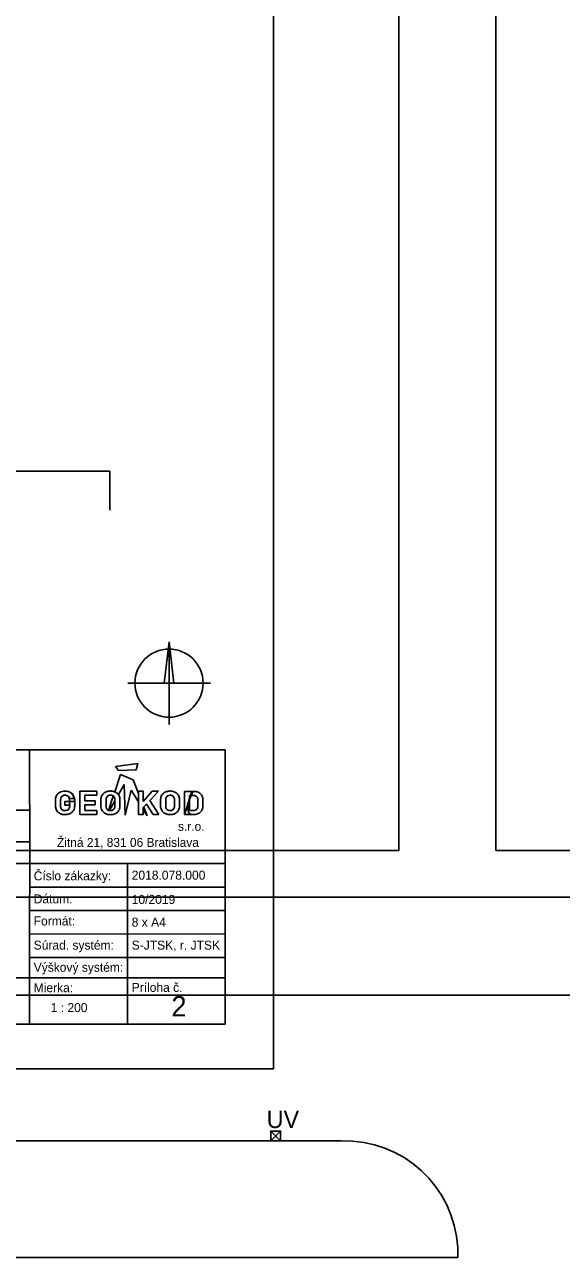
# Model space of a CAD drawing. Extents: x -264222 to -263676, y -1242344 to -1242060.
# Drawn here: x -264066.8 to -264039.2, y -1242315 to -1242251.5 of the extents above; entities that cross this region are included whole.
import ezdxf

# ---------------------------------------------------------------- set-up
doc = ezdxf.new("R2010")
doc.units = 0
for name, color, linetype in [('KOORDINACNA_SITUACIA_DSP', 7, 'Continuous'), ('PROJEKT_DRS_OBRUBNIKY_KOMUNIKACIE', 7, 'Continuous'), ('PROJEKT_DRS_UV_STAVBY', 7, 'Continuous'), ('RAM_NA_TLAC_8xA4_1-200', 7, 'Continuous'), ('ROZPISKA', 7, 'Continuous')]:
    doc.layers.add(name, color=color, linetype=linetype)

msp = doc.modelspace()

# ---------------------------------------------------------------- linework, layer by layer
at = {"layer": 'KOORDINACNA_SITUACIA_DSP'}
for p, q in [((-264062.458, -1242274.482), (-264102.778, -1242274.482)), ((-264062.458, -1242276.492), (-264062.458, -1242274.482))]:
    msp.add_line(p, q, dxfattribs=at)
at = {"layer": 'PROJEKT_DRS_OBRUBNIKY_KOMUNIKACIE'}
for p, q in [((-263971.068, -1242301.482), (-264112.961, -1242301.482)), ((-264050.531, -1242308.982), (-264119.571, -1242308.982)), ((-264115.886, -1242314.982), (-264044.531, -1242314.982)), ((-264044.531, -1242314.982), (-264044.531, -1242314.482))]:
    msp.add_line(p, q, dxfattribs=at)
for points in [[(-264117.668, -1242187.932), (-264047.568, -1242187.932), (-264047.568, -1242294.032), (-264117.668, -1242294.032), (-264117.668, -1242187.932)], [(-264042.568, -1242294.032), (-263972.468, -1242294.032), (-263972.468, -1242187.932), (-264042.568, -1242187.932), (-264042.568, -1242294.032)], [(-263965.143, -1242296.432), (-264120.018, -1242296.432), (-264120.282, -1242296.432)]]:
    msp.add_lwpolyline(points, dxfattribs=at)
msp.add_arc((-264050.347, -1242314.804), 5.825, 3.17009, 91.80902, dxfattribs=at)
at = {"layer": 'PROJEKT_DRS_UV_STAVBY'}
msp.add_lwpolyline([(-264054.163, -1242308.982), (-264054.163, -1242308.482), (-264053.663, -1242308.482), (-264053.663, -1242308.982), (-264054.163, -1242308.982), (-264053.663, -1242308.482), (-264054.163, -1242308.482), (-264053.663, -1242308.982)], dxfattribs=at)
at = {"layer": 'RAM_NA_TLAC_8xA4_1-200'}
msp.add_lwpolyline([(-264222.03, -1242186.466), (-264054.03, -1242186.466), (-264054.03, -1242305.266), (-264222.03, -1242305.266)], close=True, dxfattribs=at)
at = {"layer": 'ROZPISKA'}
for p, q in [((-264059.408, -1242283.272), (-264059.66, -1242285.404)), ((-264059.408, -1242283.272), (-264059.408, -1242287.536)), ((-264059.408, -1242283.272), (-264059.155, -1242285.403)), ((-264061.539, -1242285.404), (-264057.276, -1242285.403)), ((-264093.815, -1242288.848), (-264056.508, -1242288.848)), ((-264066.59, -1242294.494), (-264066.592, -1242288.847)), ((-264056.508, -1242288.848), (-264056.508, -1242302.965)), ((-264062.207, -1242291.004), (-264061.914, -1242290.118)), ((-264061.914, -1242290.118), (-264061.264, -1242290.394)), ((-264062.444, -1242290.962), (-264062.423, -1242290.961)), ((-264061.728, -1242290.622), (-264062.019, -1242291.144)), ((-264061.671, -1242292.202), (-264061.728, -1242290.622)), ((-264061.359, -1242290.921), (-264061.671, -1242292.202)), ((-264060.989, -1242291.517), (-264061.359, -1242290.921)), ((-264061.264, -1242290.394), (-264060.989, -1242291.093)), ((-264060.735, -1242290.977), (-264060.989, -1242290.977)), ((-264060.274, -1242290.977), (-264060.735, -1242291.499)), ((-264060.735, -1242291.499), (-264060.735, -1242290.977)), ((-264060.396, -1242291.457), (-264059.957, -1242290.977)), ((-264059.957, -1242290.977), (-264060.274, -1242290.977)), ((-264064.272, -1242291.347), (-264064.537, -1242291.347)), ((-264064.537, -1242291.347), (-264064.272, -1242291.347)), ((-264062.279, -1242291.223), (-264062.522, -1242291.959)), ((-264062.44, -1242291.175), (-264062.426, -1242291.175)), ((-264062.44, -1242291.175), (-264062.426, -1242291.175)), ((-264060.989, -1242291.093), (-264060.989, -1242291.517)), ((-264059.933, -1242292.172), (-264060.396, -1242291.457)), ((-264058.615, -1242290.98), (-264058.234, -1242290.98)), ((-264058.615, -1242292.172), (-264058.615, -1242290.98)), ((-264058.615, -1242290.98), (-264058.615, -1242292.172)), ((-264058.234, -1242290.98), (-264058.615, -1242290.98)), ((-264058.354, -1242291.187), (-264058.354, -1242291.965)), ((-264058.354, -1242291.187), (-264058.354, -1242291.965)), ((-264093.817, -1242291.946), (-264066.591, -1242291.946)), ((-264060.535, -1242292.248), (-264060.735, -1242291.927)), ((-264060.714, -1242291.793), (-264060.535, -1242292.248)), ((-264060.234, -1242292.172), (-264059.933, -1242292.172)), ((-264093.816, -1242293.587), (-264066.592, -1242293.587)), ((-264093.818, -1242294.699), (-264066.588, -1242294.696)), ((-264066.59, -1242294.494), (-264066.591, -1242298.126)), ((-264066.588, -1242294.696), (-264056.507, -1242294.696)), ((-264061.55, -1242294.697), (-264061.549, -1242298.328)), ((-264066.59, -1242295.907), (-264056.508, -1242295.908)), ((-264066.593, -1242297.116), (-264056.507, -1242297.116)), ((-264066.593, -1242298.327), (-264056.506, -1242298.328)), ((-264066.591, -1242298.126), (-264066.591, -1242302.964)), ((-264061.549, -1242298.328), (-264061.548, -1242302.964)), ((-264066.591, -1242299.537), (-264056.507, -1242299.536)), ((-264093.816, -1242300.585), (-264056.507, -1242300.584)), ((-264093.816, -1242302.965), (-264056.508, -1242302.965))]:
    msp.add_line(p, q, dxfattribs=at)
for points in [[(-264059.408, -1242283.272), (-264059.155, -1242285.403), (-264059.408, -1242285.403)], [(-264062.173, -1242289.707), (-264061.017, -1242289.541), (-264061.098, -1242289.871), (-264062.019, -1242289.9)], [(-264064.01, -1242290.971), (-264064.01, -1242292.172), (-264063.131, -1242292.172), (-264063.131, -1242291.96), (-264063.746, -1242291.96), (-264063.746, -1242291.673), (-264063.22, -1242291.673), (-264063.22, -1242291.464), (-264063.746, -1242291.464), (-264063.746, -1242291.184), (-264063.131, -1242291.184), (-264063.131, -1242290.971)]]:
    msp.add_lwpolyline(points, close=True, dxfattribs=at)
for points in [[(-264060.989, -1242290.977), (-264060.989, -1242292.172), (-264060.735, -1242292.172), (-264060.735, -1242291.815), (-264060.565, -1242291.635), (-264060.234, -1242292.172)], [(-264064.528, -1242291.7), (-264064.778, -1242291.7), (-264064.778, -1242291.502), (-264064.269, -1242291.502)], [(-264064.269, -1242291.502), (-264064.778, -1242291.502), (-264064.778, -1242291.7), (-264064.528, -1242291.7)], [(-264062.481, -1242291.97), (-264062.2, -1242291.467)], [(-264062.2, -1242291.467), (-264062.2, -1242291.441), (-264062.201, -1242291.408), (-264062.204, -1242291.378), (-264062.209, -1242291.349), (-264062.216, -1242291.322), (-264062.226, -1242291.293), (-264062.242, -1242291.264), (-264062.259, -1242291.242), (-264062.279, -1242291.223)], [(-264062.019, -1242291.144), (-264062.028, -1242291.133), (-264062.043, -1242291.116), (-264062.058, -1242291.101), (-264062.076, -1242291.085), (-264062.093, -1242291.071), (-264062.113, -1242291.057), (-264062.129, -1242291.046), (-264062.147, -1242291.035), (-264062.168, -1242291.023), (-264062.187, -1242291.012), (-264062.207, -1242291.004)], [(-264062.522, -1242291.959), (-264062.515, -1242291.961), (-264062.507, -1242291.964), (-264062.5, -1242291.966), (-264062.493, -1242291.968), (-264062.486, -1242291.969), (-264062.481, -1242291.97)], [(-264060.735, -1242291.927), (-264060.735, -1242291.815), (-264060.714, -1242291.793)]]:
    msp.add_lwpolyline(points, dxfattribs=at)
msp.add_circle((-264059.408, -1242285.404), 1.756, dxfattribs=at)
for points in [[(-264064.269, -1242291.502), (-264064.268, -1242291.654), (-264064.272, -1242291.79), (-264064.299, -1242291.91), (-264064.358, -1242292.007), (-264064.447, -1242292.089), (-264064.54, -1242292.143), (-264064.665, -1242292.175), (-264064.777, -1242292.182), (-264064.894, -1242292.175), (-264065.01, -1242292.136), (-264065.112, -1242292.07), (-264065.189, -1242291.992), (-264065.24, -1242291.887), (-264065.263, -1242291.77), (-264065.267, -1242291.693), (-264065.267, -1242291.456), (-264065.259, -1242291.327), (-264065.224, -1242291.219), (-264065.166, -1242291.125), (-264065.049, -1242291.032), (-264064.925, -1242290.978), (-264064.781, -1242290.962), (-264064.63, -1242290.974), (-264064.47, -1242291.04), (-264064.346, -1242291.156), (-264064.272, -1242291.347), (-264064.269, -1242291.502), (-264064.272, -1242291.347)], [(-264064.272, -1242291.347), (-264064.346, -1242291.156), (-264064.47, -1242291.04), (-264064.63, -1242290.974), (-264064.781, -1242290.962), (-264064.925, -1242290.978), (-264065.049, -1242291.032), (-264065.166, -1242291.125), (-264065.224, -1242291.219), (-264065.259, -1242291.327), (-264065.267, -1242291.456), (-264065.267, -1242291.693), (-264065.263, -1242291.77), (-264065.24, -1242291.887), (-264065.189, -1242291.992), (-264065.112, -1242292.07), (-264065.01, -1242292.136), (-264064.894, -1242292.175), (-264064.777, -1242292.182), (-264064.665, -1242292.175), (-264064.54, -1242292.143), (-264064.447, -1242292.089), (-264064.358, -1242292.007), (-264064.299, -1242291.91), (-264064.272, -1242291.79), (-264064.268, -1242291.654), (-264064.269, -1242291.502), (-264064.272, -1242291.347), (-264064.269, -1242291.502)], [(-264062.423, -1242290.961), (-264062.417, -1242290.961), (-264062.381, -1242290.96), (-264062.314, -1242290.976), (-264062.224, -1242290.992), (-264062.139, -1242291.039), (-264062.062, -1242291.092), (-264061.998, -1242291.167), (-264061.962, -1242291.25), (-264061.938, -1242291.342), (-264061.939, -1242291.487), (-264061.935, -1242291.636), (-264061.938, -1242291.782), (-264061.951, -1242291.875), (-264061.986, -1242291.952), (-264062.03, -1242292.02), (-264062.09, -1242292.072), (-264062.155, -1242292.12), (-264062.236, -1242292.152), (-264062.324, -1242292.178), (-264062.419, -1242292.184), (-264062.508, -1242292.178), (-264062.588, -1242292.171), (-264062.656, -1242292.14), (-264062.721, -1242292.102), (-264062.783, -1242292.062), (-264062.838, -1242292.004), (-264062.883, -1242291.926), (-264062.915, -1242291.831), (-264062.928, -1242291.675), (-264062.914, -1242291.529), (-264062.922, -1242291.389), (-264062.91, -1242291.31), (-264062.892, -1242291.232), (-264062.853, -1242291.162), (-264062.803, -1242291.105), (-264062.749, -1242291.055), (-264062.681, -1242291.018), (-264062.603, -1242290.983), (-264062.521, -1242290.966), (-264062.467, -1242290.963), (-264062.444, -1242290.962)], [(-264059.348, -1242290.961), (-264059.436, -1242290.967), (-264059.53, -1242290.988), (-264059.608, -1242291.02), (-264059.671, -1242291.057), (-264059.726, -1242291.106), (-264059.774, -1242291.162), (-264059.813, -1242291.233), (-264059.833, -1242291.311), (-264059.843, -1242291.387), (-264059.843, -1242291.471), (-264059.846, -1242291.729), (-264059.836, -1242291.825), (-264059.801, -1242291.932), (-264059.756, -1242292.008), (-264059.709, -1242292.057), (-264059.641, -1242292.104), (-264059.58, -1242292.139), (-264059.514, -1242292.166), (-264059.434, -1242292.178), (-264059.348, -1242292.182), (-264059.246, -1242292.174), (-264059.155, -1242292.149), (-264059.084, -1242292.118), (-264059.012, -1242292.069), (-264058.957, -1242292.018), (-264058.914, -1242291.954), (-264058.879, -1242291.872), (-264058.865, -1242291.788), (-264058.861, -1242291.684), (-264058.863, -1242291.436), (-264058.867, -1242291.34), (-264058.887, -1242291.254), (-264058.928, -1242291.166), (-264058.983, -1242291.1), (-264059.069, -1242291.037), (-264059.147, -1242290.998), (-264059.239, -1242290.975), (-264059.33, -1242290.961), (-264059.348, -1242290.961), (-264059.348, -1242290.961), (-264059.348, -1242290.961)], [(-264064.535, -1242291.347), (-264064.56, -1242291.281), (-264064.619, -1242291.217), (-264064.698, -1242291.18), (-264064.778, -1242291.174), (-264064.858, -1242291.184), (-264064.922, -1242291.221), (-264064.968, -1242291.272), (-264064.992, -1242291.326), (-264064.994, -1242291.408), (-264065, -1242291.497), (-264065.001, -1242291.604), (-264065, -1242291.73), (-264064.99, -1242291.823), (-264064.955, -1242291.897), (-264064.904, -1242291.94), (-264064.844, -1242291.965), (-264064.78, -1242291.973), (-264064.704, -1242291.969), (-264064.625, -1242291.936), (-264064.568, -1242291.882), (-264064.535, -1242291.819), (-264064.527, -1242291.748), (-264064.528, -1242291.7), (-264064.535, -1242291.347), (-264064.528, -1242291.7)], [(-264064.528, -1242291.7), (-264064.527, -1242291.748), (-264064.535, -1242291.819), (-264064.568, -1242291.882), (-264064.625, -1242291.936), (-264064.704, -1242291.969), (-264064.78, -1242291.973), (-264064.844, -1242291.965), (-264064.904, -1242291.94), (-264064.955, -1242291.897), (-264064.99, -1242291.823), (-264065, -1242291.73), (-264065.001, -1242291.604), (-264065, -1242291.497), (-264064.994, -1242291.408), (-264064.992, -1242291.326), (-264064.968, -1242291.272), (-264064.922, -1242291.221), (-264064.858, -1242291.184), (-264064.778, -1242291.174), (-264064.698, -1242291.18), (-264064.619, -1242291.217), (-264064.56, -1242291.281), (-264064.535, -1242291.347), (-264064.528, -1242291.7), (-264064.535, -1242291.347)], [(-264062.426, -1242291.175), (-264062.415, -1242291.175), (-264062.387, -1242291.175), (-264062.34, -1242291.186), (-264062.287, -1242291.213), (-264062.24, -1242291.259), (-264062.21, -1242291.326), (-264062.198, -1242291.399), (-264062.2, -1242291.481), (-264062.198, -1242291.566), (-264062.201, -1242291.653), (-264062.197, -1242291.734), (-264062.208, -1242291.803), (-264062.224, -1242291.864), (-264062.263, -1242291.919), (-264062.32, -1242291.957), (-264062.381, -1242291.973), (-264062.431, -1242291.97), (-264062.476, -1242291.973), (-264062.524, -1242291.961), (-264062.572, -1242291.932), (-264062.617, -1242291.888), (-264062.648, -1242291.823), (-264062.659, -1242291.745), (-264062.655, -1242291.651), (-264062.657, -1242291.545), (-264062.655, -1242291.444), (-264062.652, -1242291.362), (-264062.639, -1242291.297), (-264062.603, -1242291.244), (-264062.554, -1242291.203), (-264062.497, -1242291.178), (-264062.457, -1242291.175), (-264062.44, -1242291.175)], [(-264062.426, -1242291.175), (-264062.415, -1242291.175), (-264062.387, -1242291.175), (-264062.34, -1242291.186), (-264062.287, -1242291.213), (-264062.24, -1242291.259), (-264062.21, -1242291.326), (-264062.198, -1242291.399), (-264062.2, -1242291.481), (-264062.198, -1242291.566), (-264062.201, -1242291.653), (-264062.197, -1242291.734), (-264062.208, -1242291.803), (-264062.224, -1242291.864), (-264062.263, -1242291.919), (-264062.32, -1242291.957), (-264062.381, -1242291.973), (-264062.431, -1242291.97), (-264062.476, -1242291.973), (-264062.524, -1242291.961), (-264062.572, -1242291.932), (-264062.617, -1242291.888), (-264062.648, -1242291.823), (-264062.659, -1242291.745), (-264062.655, -1242291.651), (-264062.657, -1242291.545), (-264062.655, -1242291.444), (-264062.652, -1242291.362), (-264062.639, -1242291.297), (-264062.603, -1242291.244), (-264062.554, -1242291.203), (-264062.497, -1242291.178), (-264062.457, -1242291.175), (-264062.44, -1242291.175)], [(-264059.35, -1242291.175), (-264059.414, -1242291.18), (-264059.478, -1242291.207), (-264059.527, -1242291.248), (-264059.558, -1242291.295), (-264059.574, -1242291.36), (-264059.578, -1242291.432), (-264059.58, -1242291.541), (-264059.58, -1242291.664), (-264059.58, -1242291.748), (-264059.568, -1242291.823), (-264059.535, -1242291.889), (-264059.492, -1242291.932), (-264059.447, -1242291.959), (-264059.396, -1242291.971), (-264059.355, -1242291.971), (-264059.314, -1242291.971), (-264059.249, -1242291.954), (-264059.185, -1242291.911), (-264059.152, -1242291.864), (-264059.134, -1242291.805), (-264059.124, -1242291.737), (-264059.124, -1242291.66), (-264059.123, -1242291.563), (-264059.124, -1242291.475), (-264059.124, -1242291.405), (-264059.14, -1242291.319), (-264059.167, -1242291.262), (-264059.214, -1242291.215), (-264059.269, -1242291.186), (-264059.316, -1242291.176), (-264059.35, -1242291.175), (-264059.35, -1242291.175), (-264059.35, -1242291.175)], [(-264058.234, -1242290.98), (-264058.109, -1242290.98), (-264058.032, -1242290.985), (-264057.975, -1242290.996), (-264057.901, -1242291.021), (-264057.83, -1242291.061), (-264057.759, -1242291.127), (-264057.707, -1242291.203), (-264057.681, -1242291.273), (-264057.665, -1242291.383), (-264057.664, -1242291.437), (-264057.663, -1242291.675), (-264057.666, -1242291.753), (-264057.672, -1242291.816), (-264057.683, -1242291.884), (-264057.717, -1242291.967), (-264057.776, -1242292.044), (-264057.864, -1242292.113), (-264057.936, -1242292.145), (-264058.009, -1242292.165), (-264058.07, -1242292.172), (-264058.092, -1242292.172), (-264058.615, -1242292.172), (-264058.234, -1242290.98), (-264058.615, -1242292.172)], [(-264058.615, -1242292.172), (-264058.092, -1242292.172), (-264058.07, -1242292.172), (-264058.009, -1242292.165), (-264057.936, -1242292.145), (-264057.864, -1242292.113), (-264057.776, -1242292.044), (-264057.717, -1242291.967), (-264057.683, -1242291.884), (-264057.672, -1242291.816), (-264057.666, -1242291.753), (-264057.663, -1242291.675), (-264057.664, -1242291.437), (-264057.665, -1242291.383), (-264057.681, -1242291.273), (-264057.707, -1242291.203), (-264057.759, -1242291.127), (-264057.83, -1242291.061), (-264057.901, -1242291.021), (-264057.975, -1242290.996), (-264058.032, -1242290.985), (-264058.109, -1242290.98), (-264058.234, -1242290.98), (-264058.615, -1242292.172), (-264058.234, -1242290.98)], [(-264058.354, -1242291.965), (-264058.278, -1242291.965), (-264058.198, -1242291.966), (-264058.115, -1242291.965), (-264058.1, -1242291.966), (-264058.07, -1242291.959), (-264058.022, -1242291.935), (-264057.961, -1242291.892), (-264057.932, -1242291.818), (-264057.923, -1242291.738), (-264057.924, -1242291.626), (-264057.923, -1242291.498), (-264057.924, -1242291.394), (-264057.93, -1242291.324), (-264057.958, -1242291.275), (-264058.011, -1242291.225), (-264058.07, -1242291.199), (-264058.152, -1242291.187), (-264058.207, -1242291.187), (-264058.319, -1242291.188), (-264058.354, -1242291.187)], [(-264058.354, -1242291.965), (-264058.278, -1242291.965), (-264058.198, -1242291.966), (-264058.115, -1242291.965), (-264058.1, -1242291.966), (-264058.07, -1242291.959), (-264058.022, -1242291.935), (-264057.961, -1242291.892), (-264057.932, -1242291.818), (-264057.923, -1242291.738), (-264057.924, -1242291.626), (-264057.923, -1242291.498), (-264057.924, -1242291.394), (-264057.93, -1242291.324), (-264057.958, -1242291.275), (-264058.011, -1242291.225), (-264058.07, -1242291.199), (-264058.152, -1242291.187), (-264058.207, -1242291.187), (-264058.319, -1242291.188), (-264058.354, -1242291.187)]]:
    msp.add_open_spline(points, degree=3, dxfattribs=at)

# ---------------------------------------------------------------- texts
at = {"layer": 'PROJEKT_DRS_UV_STAVBY'}
msp.add_text('UV', height=0.9, rotation=359.8587, dxfattribs=at).set_placement((-264054.378, -1242308.32))
at = {"layer": 'ROZPISKA'}
for s, height, p in [('s.r.o.', 0.4598, (-264058.946, -1242293.012)), ('Žitná 21, 831 06 Bratislava', 0.4598, (-264065.182, -1242293.84)), ('Číslo zákazky:', 0.46361, (-264066.383, -1242295.562)), ('Dátum:', 0.4637, (-264066.383, -1242296.749)), ('Formát:', 0.4637, (-264066.383, -1242297.888)), ('Súrad. systém:', 0.46361, (-264066.383, -1242299.133)), ('Výškový systém:', 0.46361, (-264066.383, -1242300.272)), ('Mierka:', 0.4637, (-264066.383, -1242301.325)), ('Príloha č.', 0.4636, (-264061.332, -1242301.31))]:
    msp.add_text(s, height=height, rotation=0.00155, dxfattribs=at).set_placement(p)
for s, height, p in [('2018.078.000', 0.4644, (-264061.332, -1242295.529)), ('10/2019', 0.4644, (-264061.332, -1242296.778)), ('8 x A4', 0.4644, (-264061.332, -1242297.949)), ('S-JTSK, r. JTSK', 0.4644, (-264061.332, -1242299.135)), ('2', 1.045, (-264059.285, -1242302.572)), ('1 : 200', 0.4644, (-264065.507, -1242302.351))]:
    msp.add_text(s, height=height, dxfattribs=at).set_placement(p)

doc.saveas('drawing.dxf')
